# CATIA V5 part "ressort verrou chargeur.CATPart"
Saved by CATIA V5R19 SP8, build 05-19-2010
Part number: ressort verrou chargeur
Bounding box of the stored display mesh (mm): x -0.5 to 0.5, y 87.061 to 97.057, z -9.132 to 31.364
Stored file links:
  C:\Users\Arthur\Desktop\Catia parts\GLOCK\Poignée\ressort verrou chargeur.CATPart
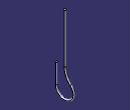
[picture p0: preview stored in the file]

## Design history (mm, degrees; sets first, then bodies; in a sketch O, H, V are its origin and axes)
Set1
  Sketch1 on yz-plane, origin (0, 0, 0), H (0, 1, 0), V (0, 0, 1)
    line L1 (92.0608, 31.3636) -> (92.0608, 6.0409)
    point P1 (92.0608, 31.3636)
    arc A1 centre (92.0608, -4.1364) radius 4.5 from (87.5608, -4.1364) to (95.089, -0.8078) ccw
    point P3 (92.0608, -4.1364)
    point P4 (87.5608, -4.1364)
    point P5 (95.089, -0.8078)
    line L2 (87.5608, -4.1364) -> (87.5608, 5.8636)
    point P6 (87.5608, -4.1364)
    construction line L3 (70.2456, -4.1364) -> (168.1084, -4.1364)
    arc A2 centre (101.3195, 6.0409) radius 9.2587 from (92.0608, 6.0409) to (95.089, -0.8078) ccw
    point P11 (95.089, -0.8078)
    axis line L4 (92.0608, 75.4182) -> (92.0608, -9.4229)
    radius A1 = 4.5
    distance P1 A1 = 40
    length L2 = 10
    vertical: L1 V, L2 V, L4 V
    coincidence: P6 P4, L3 P3, P4 L3, A2 P5, P11 P5, L4 P3, L1 L4
    horizontal: L3 H
    tangency: A2 L1, A1 A2
  Plane1: type OffsetPt, RefPlane xy-plane, RefPoint Sketch1.P1
  Sketch2 on Plane1, origin (0, 0, 31.3636), H (1, 0, 0), V (0, 1, 0)
    circle A1 centre (0, 92.0608) radius 0.5
    point P1 (0, 92.0608)
    reference projected point E1 (0, 92.0608) from Sketch1.P1
    radius A1 = 0.5
    coincidence: P1 E1
Body1 (main body)
  Rib1: profile Sketch2, centre curve Sketch1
